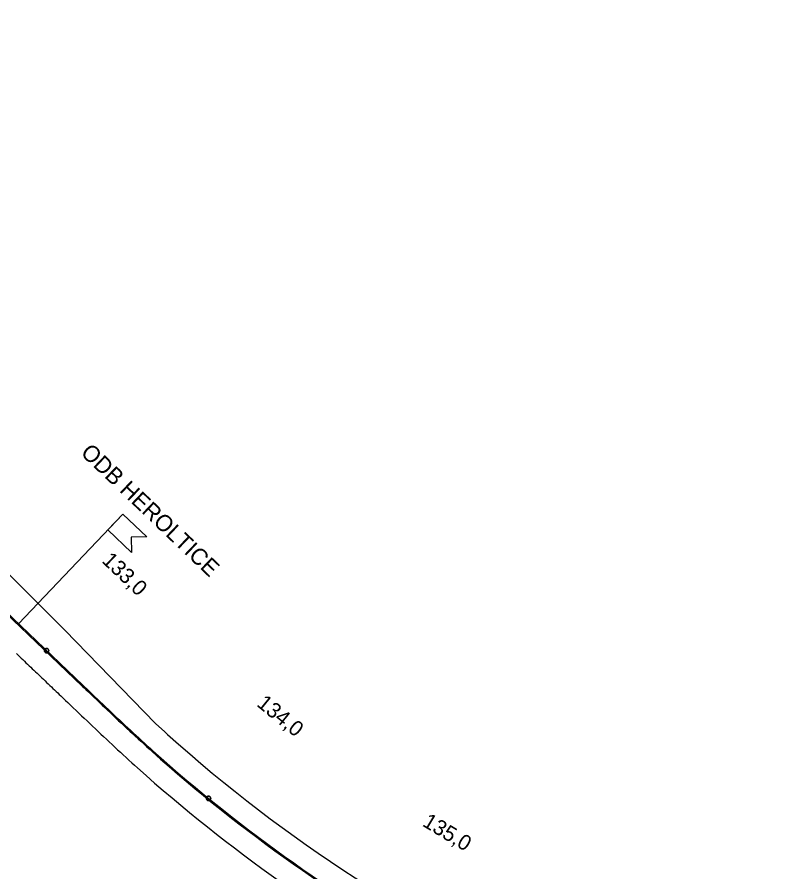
# Model space of a CAD drawing. Extents: x -670810 to -649614, y -1131928 to -1115069.
# Drawn here: x -664978 to -661499, y -1127234 to -1123337 of the extents above; entities that cross this region are included whole.
import ezdxf

# ---------------------------------------------------------------- set-up
doc = ezdxf.new("R2010")
doc.units = 0
for name, color, linetype in [('519 Var SK-4 Praporky stanic', 7, 'Continuous'), ('hranice_VRT_ZUR_Vysocina', 7, 'Continuous'), ('Situace - Osa koleje 2D', 7, 'Continuous'), ('Situace - Osa koleje tunel 2D', 7, 'Continuous'), ('Staničení - hlavní staničení + kolečka 1k', 7, 'Continuous')]:
    doc.layers.add(name, color=color, linetype=linetype)

# ---------------------------------------------------------------- blocks, each defined once
blk = doc.blocks.new('Sit10Kruh_110')
at = {"layer": 'Staničení - hlavní staničení + kolečka 1k'}
blk.add_lwpolyline([(10, 0), (10, 0.6), (9.9, 1.3), (9.8, 1.9), (9.7, 2.5), (9.5, 3.1), (9.3, 3.7), (9, 4.3), (8.8, 4.8), (8.4, 5.4), (8.1, 5.9), (7.7, 6.4), (7.3, 6.8), (6.8, 7.3), (6.4, 7.7), (5.9, 8.1), (5.4, 8.4), (4.8, 8.8), (4.3, 9), (3.7, 9.3), (3.1, 9.5), (2.5, 9.7), (1.9, 9.8), (1.3, 9.9), (0.6, 10), (0, 10), (-0.6, 10), (-1.3, 9.9), (-1.9, 9.8), (-2.5, 9.7), (-3.1, 9.5), (-3.7, 9.3), (-4.3, 9), (-4.8, 8.8), (-5.4, 8.4), (-5.9, 8.1), (-6.4, 7.7), (-6.8, 7.3), (-7.3, 6.8), (-7.7, 6.4), (-8.1, 5.9), (-8.4, 5.4), (-8.8, 4.8), (-9, 4.3), (-9.3, 3.7), (-9.5, 3.1), (-9.7, 2.5), (-9.8, 1.9), (-9.9, 1.3), (-10, 0.6), (-10, 0), (-10, -0.6), (-9.9, -1.3), (-9.8, -1.9), (-9.7, -2.5), (-9.5, -3.1), (-9.3, -3.7), (-9, -4.3), (-8.8, -4.8), (-8.4, -5.4), (-8.1, -5.9), (-7.7, -6.4), (-7.3, -6.8), (-6.8, -7.3), (-6.4, -7.7), (-5.9, -8.1), (-5.4, -8.4), (-4.8, -8.8), (-4.3, -9), (-3.7, -9.3), (-3.1, -9.5), (-2.5, -9.7), (-1.9, -9.8), (-1.3, -9.9), (-0.6, -10), (0, -10), (0.6, -10), (1.3, -9.9), (1.9, -9.8), (2.5, -9.7), (3.1, -9.5), (3.7, -9.3), (4.3, -9), (4.8, -8.8), (5.4, -8.4), (5.9, -8.1), (6.4, -7.7), (6.8, -7.3), (7.3, -6.8), (7.7, -6.4), (8.1, -5.9), (8.4, -5.4), (8.8, -4.8), (9, -4.3), (9.3, -3.7), (9.5, -3.1), (9.7, -2.5), (9.8, -1.9), (9.9, -1.3)], close=True, dxfattribs=at)
blk.add_circle((0, 0), 10, dxfattribs=at)
blk = doc.blocks.new('Sit10Kruh_111')
at = {"layer": 'Staničení - hlavní staničení + kolečka 1k'}
blk.add_lwpolyline([(10, 0), (10, 0.6), (9.9, 1.3), (9.8, 1.9), (9.7, 2.5), (9.5, 3.1), (9.3, 3.7), (9, 4.3), (8.8, 4.8), (8.4, 5.4), (8.1, 5.9), (7.7, 6.4), (7.3, 6.8), (6.8, 7.3), (6.4, 7.7), (5.9, 8.1), (5.4, 8.4), (4.8, 8.8), (4.3, 9), (3.7, 9.3), (3.1, 9.5), (2.5, 9.7), (1.9, 9.8), (1.3, 9.9), (0.6, 10), (0, 10), (-0.6, 10), (-1.3, 9.9), (-1.9, 9.8), (-2.5, 9.7), (-3.1, 9.5), (-3.7, 9.3), (-4.3, 9), (-4.8, 8.8), (-5.4, 8.4), (-5.9, 8.1), (-6.4, 7.7), (-6.8, 7.3), (-7.3, 6.8), (-7.7, 6.4), (-8.1, 5.9), (-8.4, 5.4), (-8.8, 4.8), (-9, 4.3), (-9.3, 3.7), (-9.5, 3.1), (-9.7, 2.5), (-9.8, 1.9), (-9.9, 1.3), (-10, 0.6), (-10, 0), (-10, -0.6), (-9.9, -1.3), (-9.8, -1.9), (-9.7, -2.5), (-9.5, -3.1), (-9.3, -3.7), (-9, -4.3), (-8.8, -4.8), (-8.4, -5.4), (-8.1, -5.9), (-7.7, -6.4), (-7.3, -6.8), (-6.8, -7.3), (-6.4, -7.7), (-5.9, -8.1), (-5.4, -8.4), (-4.8, -8.8), (-4.3, -9), (-3.7, -9.3), (-3.1, -9.5), (-2.5, -9.7), (-1.9, -9.8), (-1.3, -9.9), (-0.6, -10), (0, -10), (0.6, -10), (1.3, -9.9), (1.9, -9.8), (2.5, -9.7), (3.1, -9.5), (3.7, -9.3), (4.3, -9), (4.8, -8.8), (5.4, -8.4), (5.9, -8.1), (6.4, -7.7), (6.8, -7.3), (7.3, -6.8), (7.7, -6.4), (8.1, -5.9), (8.4, -5.4), (8.8, -4.8), (9, -4.3), (9.3, -3.7), (9.5, -3.1), (9.7, -2.5), (9.8, -1.9), (9.9, -1.3)], close=True, dxfattribs=at)
blk.add_circle((0, 0), 10, dxfattribs=at)

msp = doc.modelspace()

# ---------------------------------------------------------------- linework, layer by layer
at = {"layer": '519 Var SK-4 Praporky stanic'}
msp.add_line((-664972.1, -1126102.6), (-664495.4, -1125602.7), dxfattribs=at)
msp.add_lwpolyline([(-664495.4, -1125602.7), (-664386.8, -1125706.2), (-664457.5, -1125707.9), (-664455.8, -1125778.5), (-664564.4, -1125675)], close=True, dxfattribs=at)
at = {"layer": 'hranice_VRT_ZUR_Vysocina'}
for points in [[(-665993.2, -1124977.6), (-665600.9, -1125324.5), (-665173.4, -1125720.6), (-664760.4, -1126131.5), (-664347, -1126557.9)], [(-664981, -1126238.8), (-664973.8, -1126245.7), (-664966.6, -1126252.6), (-664959.3, -1126259.5), (-664952.1, -1126266.4), (-664944.8, -1126273.3), (-664937.6, -1126280.2), (-664930.4, -1126287.1), (-664923.1, -1126294), (-664915.9, -1126300.9), (-664908.7, -1126307.8), (-664901.4, -1126314.7), (-664894.2, -1126321.6), (-664887, -1126328.5), (-664879.7, -1126335.4), (-664872.5, -1126342.3), (-664865.2, -1126349.2), (-664858, -1126356.1), (-664850.8, -1126363), (-664843.5, -1126369.9), (-664836.3, -1126376.8), (-664829.1, -1126383.7), (-664821.8, -1126390.6), (-664814.6, -1126397.5), (-664807.3, -1126404.4), (-664800.1, -1126411.3), (-664792.9, -1126418.2), (-664785.6, -1126425.1), (-664778.4, -1126432), (-664771.2, -1126438.9), (-664763.9, -1126445.8), (-664756.7, -1126452.7), (-664746.8, -1126462.2)], [(-664746.8, -1126462.2), (-664746.8, -1126462.2), (-664734.3, -1126474.1), (-664721.7, -1126486.1), (-664709.2, -1126498), (-664696.7, -1126509.9), (-664684.2, -1126521.9), (-664671.6, -1126533.8), (-664659.1, -1126545.8), (-664646.5, -1126557.7), (-664633.9, -1126569.7), (-664621.3, -1126581.6), (-664608.7, -1126593.6), (-664596.1, -1126605.5), (-664583.4, -1126617.4), (-664570.7, -1126629.4), (-664558, -1126641.3), (-664545.2, -1126653.2), (-664532.5, -1126665.1), (-664519.6, -1126677), (-664506.8, -1126688.9), (-664493.9, -1126700.7), (-664481, -1126712.6), (-664468.1, -1126724.4), (-664455.1, -1126736.1), (-664442.1, -1126747.9), (-664429.1, -1126759.5), (-664429, -1126759.6)], [(-664347, -1126557.9), (-664305, -1126595.8), (-664292.3, -1126607.3), (-664292.3, -1126607.2)]]:
    msp.add_lwpolyline(points, dxfattribs=at)
for centre, radius, start, end in [((-659686.8, -1121469.2), 6900, 228.12762, 246.0305), ((-659686.8, -1121469.3), 7104.7, 228.12694, 254.9977)]:
    msp.add_arc(centre, radius, start, end, dxfattribs=at)
at = {"layer": 'Situace - Osa koleje 2D'}
for p, q in [((-667875.9, -1123340), (-664682.6, -1126385.2)), ((-667872.7, -1123336.5), (-664677.5, -1126383.5)), ((-664978.2, -1126096.8), (-664972.1, -1126102.6))]:
    msp.add_line(p, q, dxfattribs=at)
for points in [[(-664672.3, -1126395), (-664665.2, -1126401.8), (-664652.7, -1126413.7), (-664640.2, -1126425.6), (-664627.7, -1126437.5), (-664615.2, -1126449.5), (-664602.7, -1126461.4), (-664590.2, -1126473.3), (-664577.6, -1126485.2), (-664565.1, -1126497.1), (-664552.6, -1126509), (-664540, -1126520.9), (-664527.4, -1126532.8), (-664514.9, -1126544.6), (-664502.3, -1126556.5), (-664489.7, -1126568.3), (-664477, -1126580.1), (-664464.4, -1126591.9), (-664451.7, -1126603.6), (-664439, -1126615.4), (-664426.3, -1126627.1), (-664413.5, -1126638.7), (-664400.8, -1126650.4), (-664388, -1126662), (-664375.1, -1126673.6), (-664362.3, -1126685.1)], [(-664667.3, -1126393.3), (-664662, -1126398.4), (-664649.4, -1126410.3), (-664636.9, -1126422.3), (-664624.4, -1126434.2), (-664611.9, -1126446.1), (-664599.4, -1126458), (-664586.9, -1126469.9), (-664574.4, -1126481.8), (-664561.8, -1126493.7), (-664549.3, -1126505.6), (-664536.8, -1126517.5), (-664524.2, -1126529.4), (-664511.6, -1126541.2), (-664499, -1126553.1), (-664486.4, -1126564.9), (-664473.8, -1126576.7), (-664461.2, -1126588.5), (-664448.5, -1126600.2), (-664435.8, -1126611.9), (-664423.1, -1126623.6), (-664410.3, -1126635.3), (-664397.6, -1126647), (-664384.8, -1126658.6), (-664371.9, -1126670.1), (-664359.1, -1126681.7)]]:
    msp.add_lwpolyline(points, dxfattribs=at)
for radius, start, end in [(7004.7, 228.12698, 254.99766), (7000, 228.12757, 254.99706)]:
    msp.add_arc((-659686.8, -1121469.3), radius, start, end, dxfattribs=at)
at = {"layer": 'Situace - Osa koleje tunel 2D'}
for p, q in [((-664682.6, -1126385.2), (-664677.8, -1126389.8)), ((-664677.5, -1126383.5), (-664674.5, -1126386.5))]:
    msp.add_line(p, q, dxfattribs=at)
for points in [[(-664677.8, -1126389.8), (-664672.3, -1126395)], [(-664674.5, -1126386.5), (-664667.3, -1126393.3)]]:
    msp.add_lwpolyline(points, dxfattribs=at)

# ---------------------------------------------------------------- block references
at = {"layer": 'Staničení - hlavní staničení + kolečka 1k'}
for name, p, rotation in [('Sit10Kruh_110', (-664843.6, -1126225.1), -43.640410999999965), ('Sit10Kruh_111', (-664105, -1126898.8), -39.136804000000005)]:
    msp.add_blockref(name, p, dxfattribs=dict(at, rotation=rotation))

# ---------------------------------------------------------------- texts
at = {"layer": '519 Var SK-4 Praporky stanic'}
msp.add_text('ODB HEROLTICE', height=75, rotation=316.3596, dxfattribs=at).set_placement((-664692.3, -1125328.5))
at = {"layer": 'Staničení - hlavní staničení + kolečka 1k'}
for s, rotation, p in [('133,0', 316.3596, (-664595.3, -1125819.5)), ('134,0', 320.8632, (-663889.2, -1126474.8)), ('135,0', 329.0483, (-663133.8, -1127022.1))]:
    msp.add_text(s, height=70, rotation=rotation, dxfattribs=at).set_placement(p)

doc.saveas('drawing.dxf')
